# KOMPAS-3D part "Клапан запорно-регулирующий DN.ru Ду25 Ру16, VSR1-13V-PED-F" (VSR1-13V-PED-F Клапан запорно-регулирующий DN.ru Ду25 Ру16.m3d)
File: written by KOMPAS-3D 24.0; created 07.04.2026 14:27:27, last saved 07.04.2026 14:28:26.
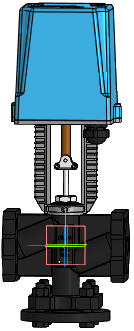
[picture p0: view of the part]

Document properties: Автор: R2D2; Полное имя файла: E:\Работа\Зайцев\Солянка\VSR1-13V-PED-F Клапан запорно-регулирующий DN.ru\DN25\VSR1-13V-PED-F Клапан запорно-регулирующий DN.ru Ду25 Ру16.m3d

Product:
- Part/product: Клапан запорно-регулирующий DN.ru Ду25 Ру16  | designation VSR1-13V-PED-F
    Масса: 7.7
    Раздел спецификации: Прочие изделия
    Примечание: D090-02888

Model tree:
1. Операция без истории:1  (labels: SHAPEOBJECT3D_ATTR_BUTT)

Expressions: VSR1-13V-PED-F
